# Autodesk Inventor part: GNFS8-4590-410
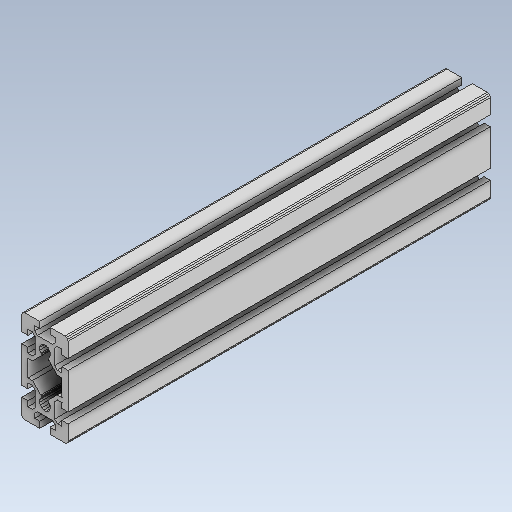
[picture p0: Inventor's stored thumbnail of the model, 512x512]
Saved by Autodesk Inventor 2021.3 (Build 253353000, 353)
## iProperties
Created: 2022-02
Part Number: GNFS8-4590-410
Material: 一般
Document SubType Name: Modeling
Designer: kengo
Density: 1 g/cm^3
Appearance: 既定
Author: kengo
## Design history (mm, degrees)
feature "GNFS8-4590-410"
node "ソリッド1"
